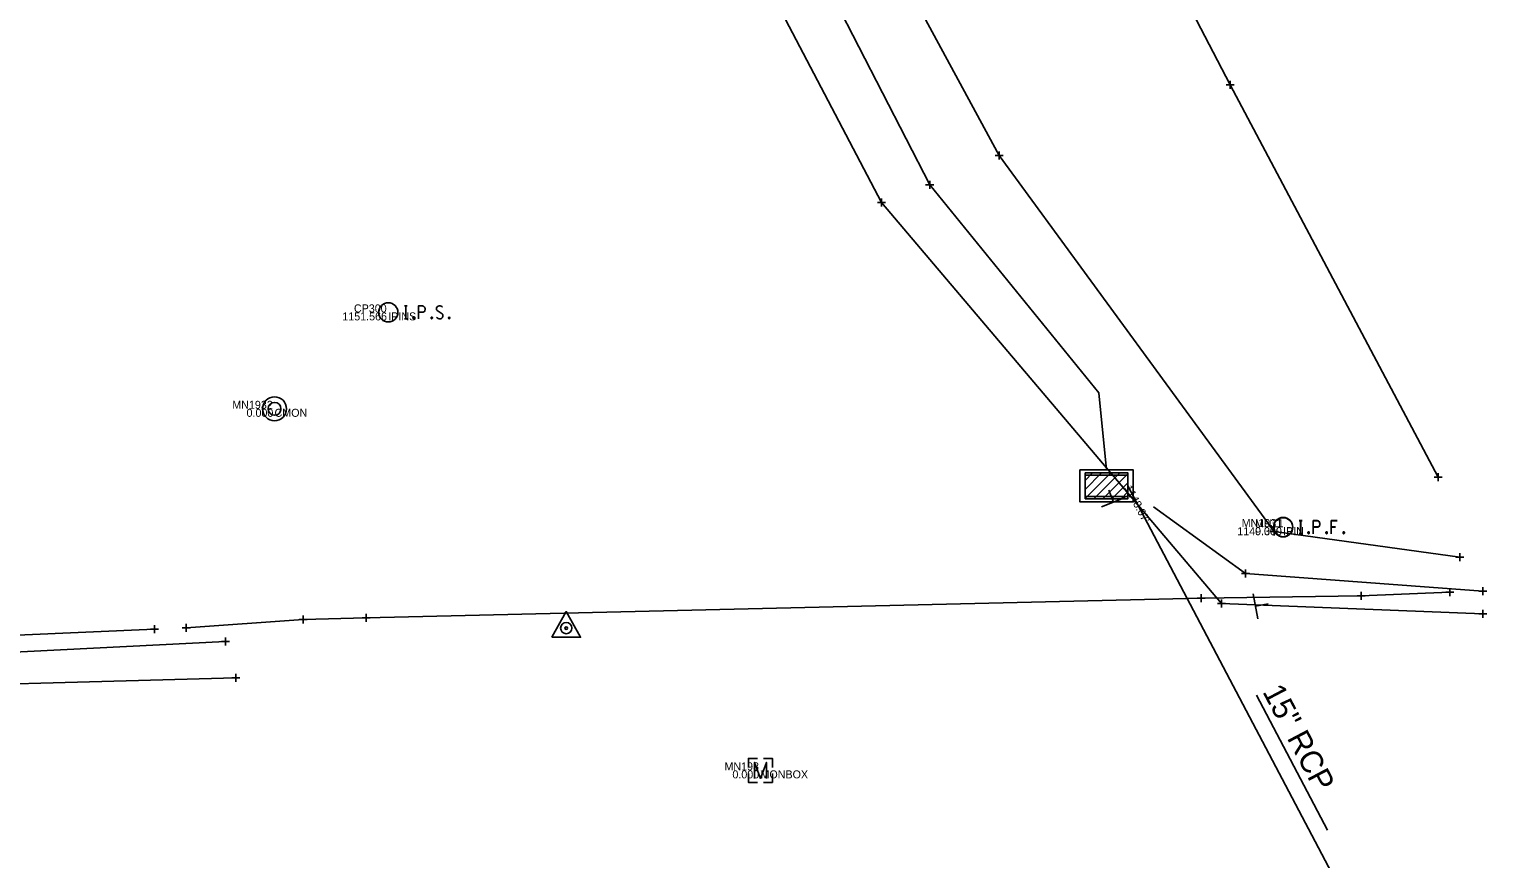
# Model space of a CAD drawing. Extents: x 2298098 to 2302860, y 557788 to 564251.
# Drawn here: x 2299294.7 to 2299476.8, y 561830.6 to 561934.3 of the extents above; entities that cross this region are included whole.
import ezdxf

# ---------------------------------------------------------------- set-up
doc = ezdxf.new("R2010")
doc.units = 0
for name, color, linetype in [('DR_X_Cells', 7, 'Continuous'), ('DR_X_Ditch', 7, 'Continuous'), ('DR_X_Storm_Sewer', 7, 'Continuous'), ('DR_X_Text', 7, 'Continuous'), ('GK_Drainage_Nodes', 7, 'Continuous'), ('RD_X_Fence', 7, 'Continuous'), ('RS_Raster1', 7, 'Continuous'), ('SC_Scratch1', 7, 'Continuous'), ('SN_X_Public', 7, 'Continuous'), ('SV_P_Aerial_Targets', 7, 'Continuous'), ('SV_X_Break_Lines', 7, 'Continuous'), ('SV_X_Mon_Cells_Found', 7, 'Continuous'), ('SV_X_Shot_Marker', 7, 'Continuous'), ('SV_X_Text_Comment', 7, 'Continuous'), ('SV_X_Text_Elevation', 7, 'Continuous'), ('SV_X_Text_Name', 7, 'Continuous'), ('UT_X_Gas', 7, 'Continuous')]:
    doc.layers.add(name, color=color, linetype=linetype)

msp = doc.modelspace()

# ---------------------------------------------------------------- linework, layer by layer
at = {"layer": 'DR_X_Cells'}
for p, q in [((2299426.64, 561875.66), (2299429.82, 561878.84)), ((2299426.64, 561876.79), (2299428.69, 561878.84)), ((2299426.64, 561877.92), (2299427.56, 561878.84)), ((2299427.72, 561875.61), (2299430.95, 561878.84)), ((2299428.85, 561875.61), (2299431.97, 561878.73)), ((2299429.98, 561875.61), (2299431.97, 561877.6)), ((2299431.11, 561875.61), (2299431.97, 561876.47))]:
    msp.add_line(p, q, dxfattribs=at)
for points in [[(2299425.97, 561879.23), (2299432.64, 561879.23), (2299432.64, 561875.23), (2299425.97, 561875.23)], [(2299426.64, 561878.84), (2299431.97, 561878.84), (2299431.97, 561875.61), (2299426.64, 561875.61)], [(2299426.64, 561878.56), (2299431.97, 561878.56), (2299431.97, 561875.89), (2299426.64, 561875.89)]]:
    msp.add_lwpolyline(points, close=True, dxfattribs=at)
at = {"layer": 'DR_X_Ditch'}
for p, q in [((2299428.32, 561888.87), (2299429.3, 561879.23)), ((2299446.68, 561866.26), (2299435.18, 561874.62)), ((2299476.32, 561864.07), (2299446.68, 561866.26))]:
    msp.add_line(p, q, dxfattribs=at)
for points in [[(2299428.32, 561888.87), (2299407.2, 561914.87), (2299383.55, 561960.87), (2299361.56, 562003.18), (2299339.22, 562047), (2299325.46, 562074.75)], [(2299217.45, 561854.09), (2299270.51, 561855.31), (2299319.22, 561857.78)]]:
    msp.add_lwpolyline(points, dxfattribs=at)
at = {"layer": 'DR_X_Storm_Sewer'}
msp.add_line((2299431.97, 561877.23), (2299467.55, 561809.69), dxfattribs=at)
at = {"layer": 'DR_X_Text'}
msp.add_line((2299456.93, 561834.19), (2299448.04, 561851.08), dxfattribs=at)
at = {"layer": 'GK_Drainage_Nodes'}
for p, q in [((2299429.3, 561879.23), (2299429.3, 561879.23)), ((2299429.3, 561878.56), (2299429.3, 561878.56)), ((2299426.64, 561877.23), (2299426.64, 561877.23)), ((2299429.3, 561877.23), (2299429.3, 561877.23)), ((2299429.3, 561877.23), (2299429.3, 561877.23)), ((2299431.97, 561877.23), (2299431.97, 561877.23)), ((2299429.3, 561875.89), (2299429.3, 561875.89)), ((2299429.3, 561875.61), (2299429.3, 561875.61)), ((2299429.3, 561875.23), (2299429.3, 561875.23))]:
    msp.add_line(p, q, dxfattribs=at)
at = {"layer": 'RD_X_Fence'}
msp.add_lwpolyline([(2299470.73, 561878.32), (2299444.74, 561927.36), (2299415.8, 561982.99), (2299397.04, 562018.9), (2299373.29, 562064.6), (2299352.56, 562103.81), (2299360.38, 562107.66)], dxfattribs=at)
at = {"layer": 'RS_Raster1'}
for points in [[(2299341.57, 561899.71), (2299341.92, 561899.71)], [(2299341.57, 561899.71), (2299341.92, 561899.71)], [(2299341.74, 561898.11), (2299341.74, 561899.71)], [(2299341.74, 561898.11), (2299341.74, 561899.71)], [(2299342.7, 561898.33), (2299342.76, 561898.33), (2299342.79, 561898.3), (2299342.82, 561898.25), (2299342.82, 561898.19), (2299342.79, 561898.14), (2299342.76, 561898.11), (2299342.7, 561898.11), (2299342.67, 561898.14), (2299342.64, 561898.19), (2299342.64, 561898.25), (2299342.67, 561898.3), (2299342.7, 561898.33)], [(2299342.7, 561898.33), (2299342.76, 561898.33), (2299342.79, 561898.3), (2299342.82, 561898.25), (2299342.82, 561898.19), (2299342.79, 561898.14), (2299342.76, 561898.11), (2299342.7, 561898.11), (2299342.67, 561898.14), (2299342.64, 561898.19), (2299342.64, 561898.25), (2299342.67, 561898.3), (2299342.7, 561898.33)], [(2299343.31, 561898.11), (2299343.31, 561899.71), (2299343.84, 561899.71), (2299343.89, 561899.7), (2299343.97, 561899.67), (2299344, 561899.65), (2299344.04, 561899.62), (2299344.08, 561899.56), (2299344.11, 561899.5), (2299344.14, 561899.4), (2299344.14, 561899.25), (2299344.13, 561899.2), (2299344.1, 561899.12), (2299344.06, 561899.03), (2299344.02, 561898.99), (2299343.98, 561898.97), (2299343.93, 561898.94), (2299343.84, 561898.93), (2299343.31, 561898.93)], [(2299343.31, 561898.11), (2299343.31, 561899.71), (2299343.84, 561899.71), (2299343.89, 561899.7), (2299343.97, 561899.67), (2299344, 561899.65), (2299344.04, 561899.62), (2299344.08, 561899.56), (2299344.11, 561899.5), (2299344.14, 561899.4), (2299344.14, 561899.25), (2299344.13, 561899.2), (2299344.1, 561899.12), (2299344.06, 561899.03), (2299344.02, 561898.99), (2299343.98, 561898.97), (2299343.93, 561898.94), (2299343.84, 561898.93), (2299343.31, 561898.93)], [(2299344.95, 561898.33), (2299345.01, 561898.33), (2299345.04, 561898.3), (2299345.07, 561898.25), (2299345.07, 561898.19), (2299345.04, 561898.14), (2299345.01, 561898.11), (2299344.95, 561898.11), (2299344.92, 561898.14), (2299344.89, 561898.19), (2299344.89, 561898.25), (2299344.92, 561898.3), (2299344.95, 561898.33)], [(2299344.95, 561898.33), (2299345.01, 561898.33), (2299345.04, 561898.3), (2299345.07, 561898.25), (2299345.07, 561898.19), (2299345.04, 561898.14), (2299345.01, 561898.11), (2299344.95, 561898.11), (2299344.92, 561898.14), (2299344.89, 561898.19), (2299344.89, 561898.25), (2299344.92, 561898.3), (2299344.95, 561898.33)], [(2299346.32, 561899.6), (2299346.3, 561899.62), (2299346.26, 561899.65), (2299346.16, 561899.69), (2299346.04, 561899.71), (2299345.96, 561899.71), (2299345.92, 561899.71), (2299345.78, 561899.67), (2299345.66, 561899.6), (2299345.58, 561899.5), (2299345.56, 561899.4), (2299345.56, 561899.32), (2299345.58, 561899.22), (2299345.67, 561899.13), (2299346.27, 561898.75), (2299346.33, 561898.7), (2299346.35, 561898.65), (2299346.37, 561898.58), (2299346.37, 561898.5), (2299346.36, 561898.43), (2299346.35, 561898.38), (2299346.33, 561898.31), (2299346.31, 561898.26), (2299346.29, 561898.23), (2299346.25, 561898.19), (2299346.22, 561898.16), (2299346.18, 561898.14), (2299346.14, 561898.12), (2299346.04, 561898.11), (2299345.89, 561898.11), (2299345.79, 561898.14), (2299345.65, 561898.23), (2299345.56, 561898.3)], [(2299346.32, 561899.6), (2299346.3, 561899.62), (2299346.26, 561899.65), (2299346.16, 561899.69), (2299346.04, 561899.71), (2299345.96, 561899.71), (2299345.92, 561899.71), (2299345.78, 561899.67), (2299345.66, 561899.6), (2299345.58, 561899.5), (2299345.56, 561899.4), (2299345.56, 561899.32), (2299345.58, 561899.22), (2299345.67, 561899.13), (2299346.27, 561898.75), (2299346.33, 561898.7), (2299346.35, 561898.65), (2299346.37, 561898.58), (2299346.37, 561898.5), (2299346.36, 561898.43), (2299346.35, 561898.38), (2299346.33, 561898.31), (2299346.31, 561898.26), (2299346.29, 561898.23), (2299346.25, 561898.19), (2299346.22, 561898.16), (2299346.18, 561898.14), (2299346.14, 561898.12), (2299346.04, 561898.11), (2299345.89, 561898.11), (2299345.79, 561898.14), (2299345.65, 561898.23), (2299345.56, 561898.3)], [(2299347.13, 561898.33), (2299347.19, 561898.33), (2299347.22, 561898.3), (2299347.26, 561898.25), (2299347.26, 561898.19), (2299347.22, 561898.14), (2299347.19, 561898.11), (2299347.13, 561898.11), (2299347.1, 561898.14), (2299347.07, 561898.19), (2299347.07, 561898.25), (2299347.1, 561898.3), (2299347.13, 561898.33)], [(2299347.13, 561898.33), (2299347.19, 561898.33), (2299347.22, 561898.3), (2299347.26, 561898.25), (2299347.26, 561898.19), (2299347.22, 561898.14), (2299347.19, 561898.11), (2299347.13, 561898.11), (2299347.1, 561898.14), (2299347.07, 561898.19), (2299347.07, 561898.25), (2299347.1, 561898.3), (2299347.13, 561898.33)], [(2299341.57, 561898.11), (2299341.92, 561898.11)], [(2299341.57, 561898.11), (2299341.92, 561898.11)]]:
    msp.add_lwpolyline(points, dxfattribs=at)
msp.add_circle((2299339.55, 561898.91), 1.2, dxfattribs=at)
msp.add_circle((2299339.55, 561898.91), 1.2, dxfattribs=at)
at = {"layer": 'SN_X_Public'}
for p, q in [((2299430.15, 561875.18), (2299429.58, 561876.68)), ((2299431.64, 561875.76), (2299428.66, 561874.61)), ((2299448.22, 561860.61), (2299447.64, 561863.75)), ((2299447.93, 561862.18), (2299449.5, 561862.47))]:
    msp.add_line(p, q, dxfattribs=at)
at = {"layer": 'SV_P_Aerial_Targets'}
msp.add_lwpolyline([(2299359.99, 561858.3), (2299363.59, 561858.3), (2299361.79, 561861.52)], close=True, dxfattribs=at)
for radius in [0.7, 0.16]:
    msp.add_circle((2299361.79, 561859.45), radius, dxfattribs=at)
at = {"layer": 'SV_X_Break_Lines'}
for points in [[(2299332.77, 562078.83), (2299346.63, 562051.21), (2299370.67, 562006.96), (2299391.28, 561964.02), (2299415.88, 561918.53), (2299450.24, 561871.53), (2299473.43, 561868.32)], [(2299476.32, 561861.23), (2299443.65, 561862.53), (2299401.2, 561912.66), (2299377.65, 561957.54), (2299355.79, 562000.1), (2299333.47, 562044.05), (2299322.09, 562073.82)], [(2299310.34, 561859.34), (2299267.41, 561857.44), (2299214.51, 561860.93)], [(2299320.5, 561853.24), (2299268.7, 561851.81), (2299217.29, 561850.89)]]:
    msp.add_lwpolyline(points, dxfattribs=at)
at = {"layer": 'SV_X_Mon_Cells_Found'}
msp.add_line((2299386.06, 561841.67), (2299386.06, 561841.67), dxfattribs=at)
for points in [[(2299453.38, 561872.88), (2299453.73, 561872.88)], [(2299453.38, 561872.85), (2299453.74, 561872.85)], [(2299453.55, 561871.28), (2299453.55, 561872.88)], [(2299453.56, 561871.25), (2299453.56, 561872.85)], [(2299455.12, 561871.28), (2299455.12, 561872.88), (2299455.65, 561872.88), (2299455.7, 561872.87), (2299455.78, 561872.84), (2299455.81, 561872.82), (2299455.85, 561872.79), (2299455.89, 561872.73), (2299455.92, 561872.67), (2299455.95, 561872.57), (2299455.95, 561872.42), (2299455.94, 561872.37), (2299455.91, 561872.29), (2299455.87, 561872.2), (2299455.82, 561872.16), (2299455.79, 561872.14), (2299455.74, 561872.11), (2299455.65, 561872.1), (2299455.12, 561872.1)], [(2299455.13, 561871.25), (2299455.13, 561872.85), (2299455.65, 561872.85), (2299455.71, 561872.84), (2299455.79, 561872.81), (2299455.82, 561872.79), (2299455.85, 561872.76), (2299455.9, 561872.7), (2299455.93, 561872.64), (2299455.95, 561872.53), (2299455.95, 561872.38), (2299455.94, 561872.33), (2299455.92, 561872.26), (2299455.87, 561872.17), (2299455.83, 561872.13), (2299455.8, 561872.11), (2299455.74, 561872.08), (2299455.65, 561872.07), (2299455.13, 561872.07)], [(2299458.13, 561872.88), (2299457.37, 561872.88), (2299457.37, 561871.28)], [(2299458.13, 561872.85), (2299457.37, 561872.85), (2299457.37, 561871.25)], [(2299453.38, 561871.28), (2299453.73, 561871.28)], [(2299453.38, 561871.25), (2299453.74, 561871.25)], [(2299454.51, 561871.5), (2299454.57, 561871.5), (2299454.6, 561871.47), (2299454.63, 561871.42), (2299454.63, 561871.36), (2299454.6, 561871.31), (2299454.57, 561871.28), (2299454.51, 561871.28), (2299454.48, 561871.31), (2299454.45, 561871.36), (2299454.45, 561871.42), (2299454.48, 561871.47), (2299454.51, 561871.5)], [(2299454.52, 561871.46), (2299454.57, 561871.46), (2299454.61, 561871.44), (2299454.64, 561871.39), (2299454.64, 561871.33), (2299454.61, 561871.28), (2299454.57, 561871.25), (2299454.52, 561871.25), (2299454.49, 561871.28), (2299454.45, 561871.33), (2299454.45, 561871.39), (2299454.49, 561871.44), (2299454.52, 561871.46)], [(2299456.76, 561871.5), (2299456.82, 561871.5), (2299456.85, 561871.47), (2299456.88, 561871.42), (2299456.88, 561871.36), (2299456.85, 561871.31), (2299456.82, 561871.28), (2299456.76, 561871.28), (2299456.73, 561871.31), (2299456.7, 561871.36), (2299456.7, 561871.42), (2299456.73, 561871.47), (2299456.76, 561871.5)], [(2299456.77, 561871.46), (2299456.82, 561871.46), (2299456.86, 561871.44), (2299456.89, 561871.39), (2299456.89, 561871.33), (2299456.86, 561871.28), (2299456.82, 561871.25), (2299456.77, 561871.25), (2299456.73, 561871.28), (2299456.7, 561871.33), (2299456.7, 561871.39), (2299456.73, 561871.44), (2299456.77, 561871.46)], [(2299457.37, 561872.1), (2299457.91, 561872.1)], [(2299457.37, 561872.07), (2299457.91, 561872.07)], [(2299458.91, 561871.5), (2299458.97, 561871.5), (2299459, 561871.47), (2299459.03, 561871.42), (2299459.03, 561871.36), (2299459, 561871.31), (2299458.97, 561871.28), (2299458.91, 561871.28), (2299458.88, 561871.31), (2299458.85, 561871.36), (2299458.85, 561871.42), (2299458.88, 561871.47), (2299458.91, 561871.5)], [(2299458.92, 561871.46), (2299458.97, 561871.46), (2299459.01, 561871.44), (2299459.04, 561871.39), (2299459.04, 561871.33), (2299459.01, 561871.28), (2299458.97, 561871.25), (2299458.92, 561871.25), (2299458.88, 561871.28), (2299458.85, 561871.33), (2299458.85, 561871.39), (2299458.88, 561871.44), (2299458.92, 561871.46)], [(2299384.56, 561842.05), (2299384.56, 561843.17), (2299385.69, 561843.17)], [(2299385.32, 561840.67), (2299385.32, 561842.67), (2299386.06, 561840.67), (2299386.8, 561842.67), (2299386.8, 561840.67)], [(2299386.42, 561843.17), (2299387.56, 561843.17), (2299387.56, 561842.05)], [(2299385.69, 561840.17), (2299384.56, 561840.17), (2299384.56, 561841.29)], [(2299387.56, 561841.29), (2299387.56, 561840.17), (2299386.42, 561840.17)]]:
    msp.add_lwpolyline(points, dxfattribs=at)
for centre, radius in [((2299325.34, 561886.86), 1.5), ((2299325.34, 561886.86), 0.8), ((2299451.36, 561872.08), 1.2), ((2299451.37, 561872.05), 1.2)]:
    msp.add_circle(centre, radius, dxfattribs=at)
at = {"layer": 'SV_X_Shot_Marker'}
for p, q in [((2299444.24, 561927.36), (2299445.24, 561927.36)), ((2299444.74, 561927.86), (2299444.74, 561926.86)), ((2299444.74, 561927.36), (2299444.74, 561927.36)), ((2299415.38, 561918.53), (2299416.38, 561918.53)), ((2299415.88, 561919.03), (2299415.88, 561918.03)), ((2299415.88, 561918.53), (2299415.88, 561918.53)), ((2299406.7, 561914.87), (2299407.7, 561914.87)), ((2299407.2, 561915.37), (2299407.2, 561914.37)), ((2299407.2, 561914.87), (2299407.2, 561914.87)), ((2299401.2, 561913.16), (2299401.2, 561912.16)), ((2299400.7, 561912.66), (2299401.7, 561912.66)), ((2299401.2, 561912.66), (2299401.2, 561912.66)), ((2299470.23, 561878.32), (2299471.23, 561878.32)), ((2299470.73, 561878.82), (2299470.73, 561877.82)), ((2299470.73, 561878.32), (2299470.73, 561878.32)), ((2299449.74, 561871.53), (2299450.74, 561871.53)), ((2299450.24, 561872.03), (2299450.24, 561871.03)), ((2299450.24, 561871.53), (2299450.24, 561871.53)), ((2299472.93, 561868.32), (2299473.93, 561868.32)), ((2299473.43, 561868.82), (2299473.43, 561867.82)), ((2299473.43, 561868.32), (2299473.43, 561868.32)), ((2299446.18, 561866.26), (2299447.18, 561866.26)), ((2299446.68, 561866.76), (2299446.68, 561865.76)), ((2299446.68, 561866.26), (2299446.68, 561866.26)), ((2299441.11, 561863.68), (2299441.11, 561862.68)), ((2299461.11, 561863.99), (2299461.11, 561862.99)), ((2299471.7, 561863.93), (2299472.7, 561863.93)), ((2299472.2, 561864.43), (2299472.2, 561863.43)), ((2299472.2, 561863.93), (2299472.2, 561863.93)), ((2299475.82, 561864.07), (2299476.82, 561864.07)), ((2299476.32, 561864.57), (2299476.32, 561863.57)), ((2299476.32, 561864.07), (2299476.32, 561864.07)), ((2299440.61, 561863.18), (2299441.61, 561863.18)), ((2299441.11, 561863.18), (2299441.11, 561863.18)), ((2299443.15, 561862.53), (2299444.15, 561862.53)), ((2299443.65, 561863.03), (2299443.65, 561862.03)), ((2299443.65, 561862.53), (2299443.65, 561862.53)), ((2299460.61, 561863.49), (2299461.61, 561863.49)), ((2299461.11, 561863.49), (2299461.11, 561863.49)), ((2299314.29, 561859.99), (2299314.29, 561858.99)), ((2299328.41, 561860.51), (2299329.41, 561860.51)), ((2299328.91, 561861.01), (2299328.91, 561860.01)), ((2299328.91, 561860.51), (2299328.91, 561860.51)), ((2299336.27, 561860.72), (2299337.27, 561860.72)), ((2299336.77, 561861.22), (2299336.77, 561860.22)), ((2299336.77, 561860.72), (2299336.77, 561860.72)), ((2299475.82, 561861.23), (2299476.82, 561861.23)), ((2299476.32, 561861.73), (2299476.32, 561860.73)), ((2299476.32, 561861.23), (2299476.32, 561861.23)), ((2299309.84, 561859.34), (2299310.84, 561859.34)), ((2299310.34, 561859.84), (2299310.34, 561858.84)), ((2299310.34, 561859.34), (2299310.34, 561859.34)), ((2299313.79, 561859.49), (2299314.79, 561859.49)), ((2299314.29, 561859.49), (2299314.29, 561859.49)), ((2299319.22, 561858.28), (2299319.22, 561857.28)), ((2299318.72, 561857.78), (2299319.72, 561857.78)), ((2299319.22, 561857.78), (2299319.22, 561857.78)), ((2299320, 561853.24), (2299321, 561853.24)), ((2299320.5, 561853.74), (2299320.5, 561852.74)), ((2299320.5, 561853.24), (2299320.5, 561853.24))]:
    msp.add_line(p, q, dxfattribs=at)
at = {"layer": 'UT_X_Gas'}
msp.add_lwpolyline([(2299314.29, 561859.49), (2299328.91, 561860.51), (2299336.77, 561860.72), (2299441.11, 561863.18), (2299461.11, 561863.49), (2299472.2, 561863.93)], dxfattribs=at)

# ---------------------------------------------------------------- texts
at = {"layer": 'DR_X_Text'}
msp.add_text('15" RCP', height=2.8, rotation=297.7859, dxfattribs=at).set_placement((2299448.74, 561851.51))
at = {"layer": 'SC_Scratch1'}
msp.add_text("1148.07'", height=1, rotation=297.7859, dxfattribs=at).set_placement((2299431.53, 561876.99))
at = {"layer": 'SV_X_Text_Comment'}
for s, p in [('IPINS', (2299339.55, 561897.91)), ('CMON', (2299325.34, 561885.86)), ('IPIN', (2299451.36, 561871.08)), ('IPIN', (2299451.37, 561871.05)), ('MONBOX', (2299386.06, 561840.67))]:
    msp.add_text(s, height=1, dxfattribs=at).set_placement(p)
at = {"layer": 'SV_X_Text_Elevation'}
for s, p in [('1151.566', (2299333.81, 561897.91)), ('0.000', (2299321.84, 561885.86)), ('1149.300', (2299445.64, 561871.05)), ('0.000', (2299447.86, 561871.08)), ('0.000', (2299382.55, 561840.67))]:
    msp.add_text(s, height=1, dxfattribs=at).set_placement(p)
at = {"layer": 'SV_X_Text_Name'}
for s, p in [('CP300', (2299335.26, 561898.91)), ('MN1932', (2299320.06, 561886.86)), ('MN1931', (2299446.19, 561872.08)), ('MN11', (2299447.85, 561872.05)), ('MN193', (2299381.56, 561841.67))]:
    msp.add_text(s, height=1, dxfattribs=at).set_placement(p)

doc.saveas('drawing.dxf')
